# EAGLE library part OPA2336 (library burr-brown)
Single-Supply, MicroPower CMOS Operational Amplifiers MicroAmplifier Series; Product Folder:OPA2336,
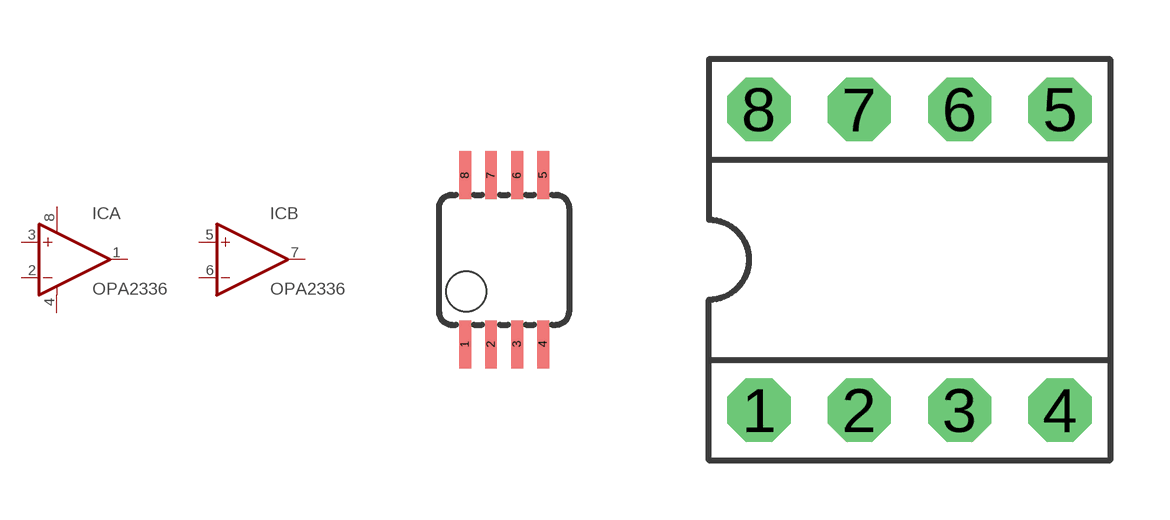
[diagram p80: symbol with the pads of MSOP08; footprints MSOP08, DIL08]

Designator prefix IC; gates A=OP-AMP+- B=OP-AMP

## OPA2336E (MF: TEXAS INSTRUMENTS; MPN: OPA2336E/250; OC_FARNELL: 1295989; OC_NEWARK: 74K3899)  [MSOP08]
1  A:OUT  out
2  A:-IN  in
3  A:+IN  in
4  A:V-  pwr
5  B:+IN  in
6  B:-IN  in
7  B:OUT  out
8  A:V+  pwr

## OPA2336P (MPN: OPA2336PA.; OC_FARNELL: 1097396; OC_NEWARK: 26M1908)  [DIL08]
Pads as for MSOP08

## OPA2336U (MPN: OPA2336UA; OC_FARNELL: 1106183; OC_NEWARK: 24M5438)  [SO08]
Pads as for MSOP08

## Footprint MSOP08 (pad centres in mm)
Mini Small Outline Package
smd 0.3 x 1.2: 1 -0.976,-2.113; 2 -0.326,-2.113; 3 0.324,-2.113; 4 0.974,-2.113; 5 0.974,2.112; 6 0.324,2.112; 7 -0.326,2.112; 8 -0.976,2.112

## Footprint DIL08 (pad centres in mm)
Dual In Line
drill 0.813 pad 1.6 octagon: 1 -3.81,-3.81; 2 -1.27,-3.81; 3 1.27,-3.81; 4 3.81,-3.81; 5 3.81,3.81; 6 1.27,3.81; 7 -1.27,3.81; 8 -3.81,3.81

## Footprint SO08 (pad centres in mm)
Small Outline Package
smd 0.61 x 2.21: 1 -1.905,-2.616; 2 -0.635,-2.616; 3 0.635,-2.616; 4 1.905,-2.616; 5 1.905,2.616; 6 0.635,2.616; 7 -0.635,2.616; 8 -1.905,2.616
